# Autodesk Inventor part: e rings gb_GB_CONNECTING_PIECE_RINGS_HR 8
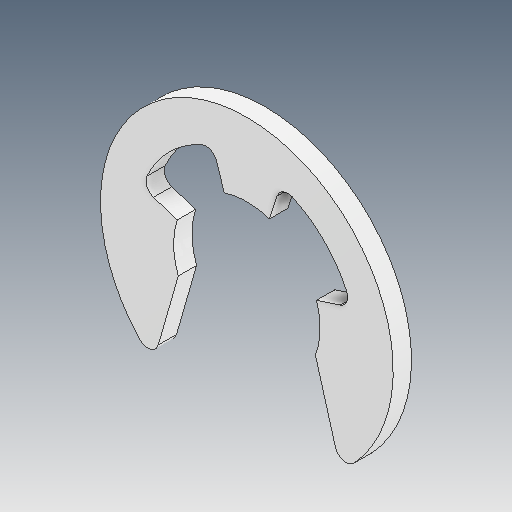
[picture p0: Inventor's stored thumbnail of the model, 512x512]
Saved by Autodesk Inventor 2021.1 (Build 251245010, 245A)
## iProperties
Created: 2021-05
Part Number: e rings gb_GB_CONNECTING_PIECE_RINGS_HR 8
Material: Ogólny
Document SubType Name: Modeling
Designer: user
Density: 1 g/cm^3
Appearance: Domyślna
Author: user
Revision Number: ÈÎºÎ
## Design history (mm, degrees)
feature "ÊäÈë1"
node "Bryła1"
